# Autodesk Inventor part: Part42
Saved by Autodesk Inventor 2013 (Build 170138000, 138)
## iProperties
Created: 2012-07
Part Number: Part42
Material: Acetal Resin, Black
Document SubType Name: Modeling
Designer: Paul
Density: 1 g/cm^3
Author: Paul
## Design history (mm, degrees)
node "User Library-Arduino Mega.SAT1"
body "Solid1"
node "Base1"
